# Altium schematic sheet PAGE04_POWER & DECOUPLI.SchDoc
size 386 x 284 mm
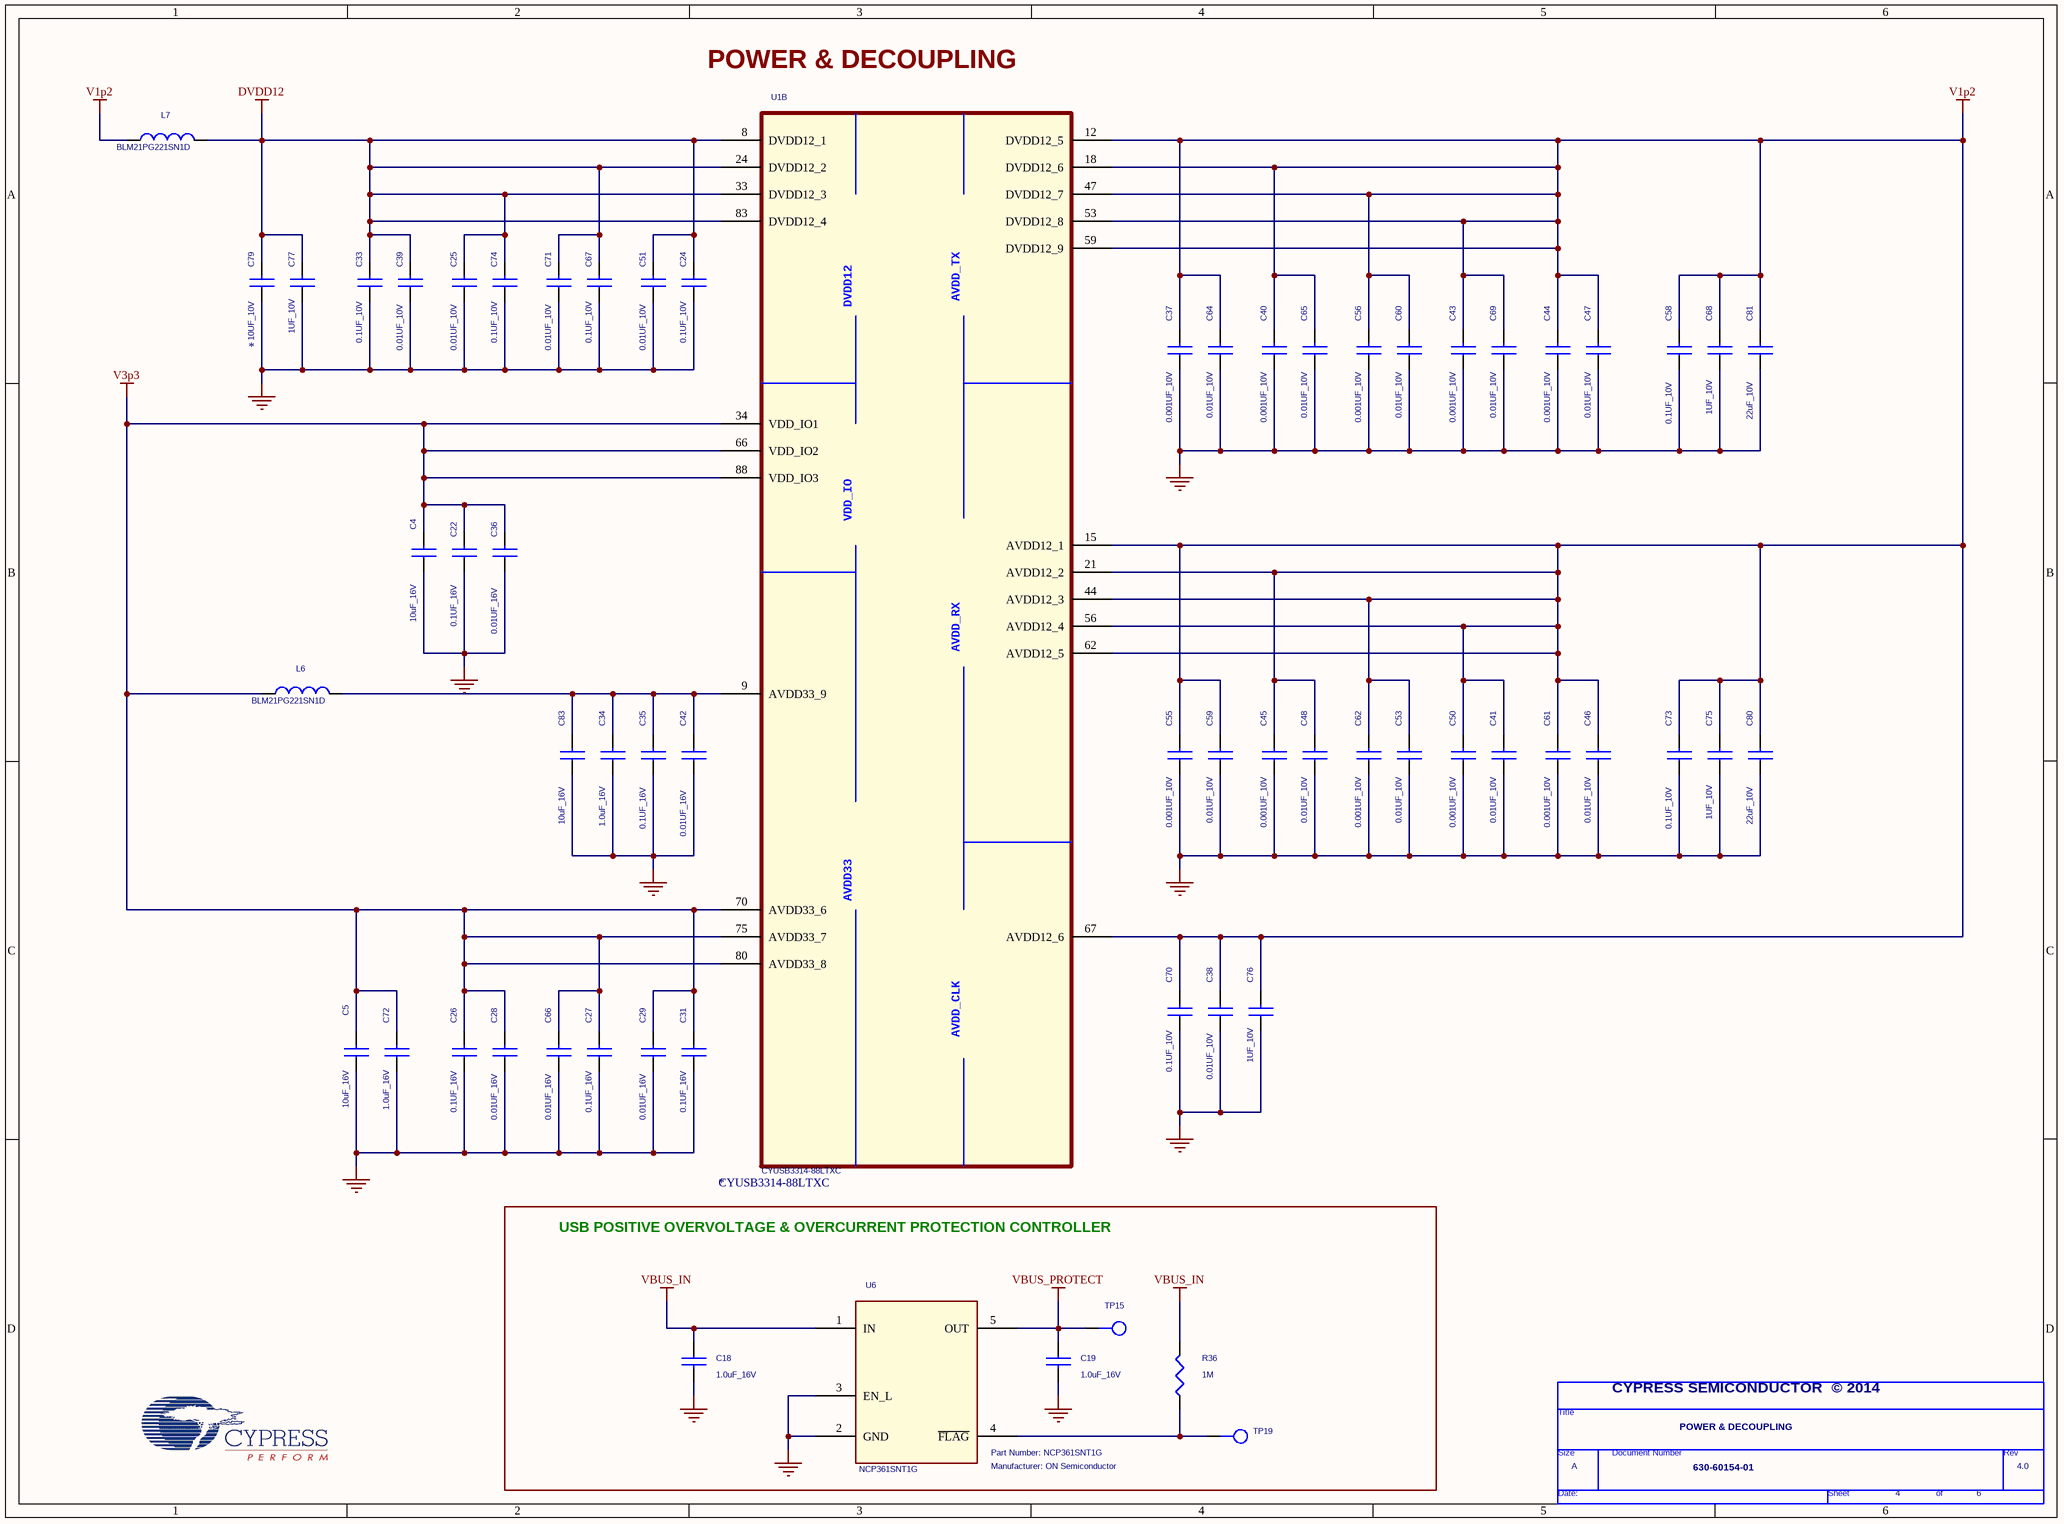
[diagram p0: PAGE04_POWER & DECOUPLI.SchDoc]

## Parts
*  Page Count: 6  Page Number: 4  Page Size: A  Title: POWER & DECOUPLING  RevCode: 4.0  Doc: 630-60154-01  (hidden comment: TitleBlock0)  (graphical)
C4  10uF_16V  [CAPC1608X90M]
C5  10uF_16V  [CAPC1608X90M]
C18  1.0uF_16V  [CAPC1608X90M]
C19  1.0uF_16V  [CAPC1608X90M]
C22  0.1UF_16V  [CAPC1005X56M]
C24  0.1UF_10V  [CAPC1005X56M]
C25  0.01UF_10V  [CAPC1005X56M]
C26  0.1UF_16V  [CAPC1005X56M]
C27  0.1UF_16V  [CAPC1005X56M]
C28  0.01UF_16V  [CAPC1005X56M]
C29  0.01UF_16V  [CAPC1005X56M]
C31  0.1UF_16V  [CAPC1005X56M]
C33  0.1UF_10V  [CAPC1005X56M]
C34  1.0uF_16V  [CAPC1005X56M]
C35  0.1UF_16V  [CAPC1005X56M]
C36  0.01UF_16V  [CAPC1005X56M]
C37  0.001UF_10V  [CAPC1005X56M]
C38  0.01UF_10V  [CAPC1005X56M]
C39  0.01UF_10V  [CAPC1005X56M]
C40  0.001UF_10V  [CAPC1005X56M]
C41  0.01UF_10V  [CAPC1005X56M]
C42  0.01UF_16V  [CAPC1005X56M]
C43  0.001UF_10V  [CAPC1005X56M]
C44  0.001UF_10V  [CAPC1005X56M]
C45  0.001UF_10V  [CAPC1005X56M]
C46  0.01UF_10V  [CAPC1005X56M]
C47  0.01UF_10V  [CAPC1005X56M]
C48  0.01UF_10V  [CAPC1005X56M]
C50  0.001UF_10V  [CAPC1005X56M]
C51  0.01UF_10V  [CAPC1005X56M]
C53  0.01UF_10V  [CAPC1005X56M]
C55  0.001UF_10V  [CAPC1005X56M]
C56  0.001UF_10V  [CAPC1005X56M]
C58  0.1UF_10V  [CAPC1005X56M]
C59  0.01UF_10V  [CAPC1005X56M]
C60  0.01UF_10V  [CAPC1005X56M]
C61  0.001UF_10V  [CAPC1005X56M]
C62  0.001UF_10V  [CAPC1005X56M]
C64  0.01UF_10V  [CAPC1005X56M]
C65  0.01UF_10V  [CAPC1005X56M]
C66  0.01UF_16V  [CAPC1005X56M]
C67  0.1UF_10V  [CAPC1005X56M]
C68  1UF_10V  [CAPC1005X56M]
C69  0.01UF_10V  [CAPC1005X56M]
C70  0.1UF_10V  [CAPC1005X56M]
C71  0.01UF_10V  [CAPC1005X56M]
C72  1.0uF_16V  [CAPC1005X56M]
C73  0.1UF_10V  [CAPC1005X56M]
C74  0.1UF_10V  [CAPC1005X56M]
C75  1UF_10V  [CAPC1005X56M]
C76  1UF_10V  [CAPC1005X56M]
C77  1UF_10V  [CAPC1005X56M]
C79  10UF_10V  [CAPC1608X90M]
C80  22uF_10V  [CAPC1608X90M]
C81  22uF_10V  [CAPC1608X90M]
C83  10uF_16V  [CAPC1608X90M]
L6  BLM21PG221SN1D  [INDC2012X105M]
L7  BLM21PG221SN1D  [INDC2012X105M]
R36  1M  [RESC1005X40M]
TP15  TP_RED  [KEYSTONE_5000]  (value not drawn)
TP19  TP_YEL  [KEYSTONE_5000]  (value not drawn)
U1  CYUSB3314-88LTXC  [QFN40P1000X1000X100-89M]  (part B of 3)
U6  NCP361SNT1G  Manufacturer: ON Semiconductor  [SOP95P275X110-5M]

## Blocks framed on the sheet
USB POSITIVE OVERVOLTAGE & OVERCURRENT PROTECTION CONTROLLER: C18 C19 R36 TP15 TP19 U6

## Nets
DVDD12: C24.2 C25.2 C33.2 C39.2 C51.2 C67.2 C71.2 C74.2 C77.2 C79.2 L7.2 U1.8(DVDD12_1) U1.24(DVDD12_2) U1.33(DVDD12_3) U1.83(DVDD12_4)
GND: C4.1 C5.1 C18.2 C19.2 C22.1 C24.1 C25.1 C26.1 C27.1 C28.1 C29.1 C31.1 C33.1 C34.1 C35.1 C36.1 C37.1 C38.1 C39.1 C40.1 C41.1 C42.1 C43.1 C44.1 C45.1 C46.1 C47.1 C48.1 C50.1 C51.1 C53.1 C55.1 C56.1 C58.1 C59.1 C60.1 C61.1 C62.1 C64.1 C65.1 C66.1 C67.1 C68.1 C69.1 C70.1 C71.1 C72.1 C73.1 C74.1 C75.1 C76.1 C77.1 C79.1 C80.1 C81.1 C83.1 U6.2(GND) U6.3(EN_L)
V1p2: C37.2 C38.2 C40.2 C41.2 C43.2 C44.2 C45.2 C46.2 C47.2 C48.2 C50.2 C53.2 C55.2 C56.2 C58.2 C59.2 C60.2 C61.2 C62.2 C64.2 C65.2 C68.2 C69.2 C70.2 C73.2 C75.2 C76.2 C80.2 C81.2 L7.1 U1.12(DVDD12_5) U1.15(AVDD12_1) U1.18(DVDD12_6) U1.21(AVDD12_2) U1.44(AVDD12_3) U1.47(DVDD12_7) U1.53(DVDD12_8) U1.56(AVDD12_4) U1.59(DVDD12_9) U1.62(AVDD12_5) U1.67(AVDD12_6)
V3p3: C4.2 C5.2 C22.2 C26.2 C27.2 C28.2 C29.2 C31.2 C36.2 C66.2 C72.2 L6.1 U1.34(VDD_IO1) U1.66(VDD_IO2) U1.70(AVDD33_6) U1.75(AVDD33_7) U1.80(AVDD33_8) U1.88(VDD_IO3)
VBUS_IN: C18.1 R36.2 U6.1(IN)
VBUS_PROTECT: C19.1 TP15.1(TP) U6.5(OUT)
NetC34_2: C34.2 C35.2 C42.2 C83.2 L6.2 U1.9(AVDD33_9)
NetR36_1: R36.1 TP19.1(TP) U6.4(~{FLAG})

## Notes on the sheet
- POWER & DECOUPLING
- CYPRESS SEMICONDUCTOR  © 2014

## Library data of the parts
C4 C5 C22 C24-C29 C31 C33-C48 C50 C51 C53 C55 C56 C58-C62 C64-C77 C79-C81 C83 = CAPACITOR NON-POL
C18 C19 = CAP: CAP - CER, 1uF, 10V, +/-10%, X5R, 0402; Part Class: CAPACITORS; Num Pins: 2; Item Num: P03-15479R
L6 L7 = INDUCTOR: FERRITE CHIP 220 OHM 2A 0805; Manufacturer: Murata; DEVICE: L4
R36 = R: RES 1.00M OHM 1/10W 1% 0402 SMD; Manufacturer: Panasonic; Part Number: ERJ-2RKF1004X
TP15 = TP: TEST POINT PC MINI .040"D RED; PART_NUMBER: 5000; Manufacturer: Keystone
TP19 = TP: TEST POINT PC MINI .040"D RED; Manufacturer: Keystone; PART_NUMBER: 5000
U1 = CYUSB3314-88LTXC_2
U6 = NCP361SNT1G_0: IC USB POS OVP/OC_TSOP5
